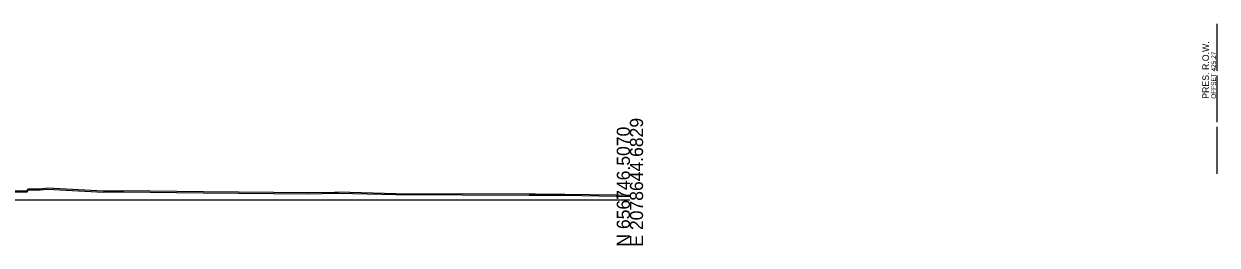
# Model space of a CAD drawing. Extents: x 5868 to 6683, y 2883 to 19120.
# Drawn here: x 6364.5 to 6619, y 18435.4 to 18482.6 of the extents above; entities that cross this region are included whole.
import ezdxf

# ---------------------------------------------------------------- set-up
doc = ezdxf.new("R2010")
doc.units = 0
for name, color, linetype in [('DESIGN - SHEET - Light Grid', 7, 'Continuous'), ('SURVEY - GROUND - Bottom of Topsoil Layer', 7, 'Continuous'), ('SURVEY - GROUND - Top of Ground', 7, 'Continuous'), ('SURVEY - PROPERTY - ROW Lines', 7, 'Continuous'), ('SURVEY - PROPERTY - ROW Lines Text', 7, 'Continuous')]:
    doc.layers.add(name, color=color, linetype=linetype)

msp = doc.modelspace()

# ---------------------------------------------------------------- linework, layer by layer
at = {"layer": 'DESIGN - SHEET - Light Grid'}
msp.add_line((6193.78, 18445.07), (6493.78, 18445.07), dxfattribs=at)
at = {"layer": 'SURVEY - GROUND - Bottom of Topsoil Layer'}
for p, q in [((6353.8, 18446.69), (6365.21, 18446.8)), ((6365.21, 18446.8), (6365.47, 18447.17)), ((6365.47, 18447.17), (6367.99, 18447.18)), ((6367.99, 18447.18), (6369.56, 18447.35)), ((6369.56, 18447.35), (6381.49, 18446.73)), ((6381.49, 18446.73), (6382.78, 18446.75)), ((6382.78, 18446.75), (6385.76, 18446.79)), ((6385.76, 18446.79), (6402.82, 18446.58)), ((6402.82, 18446.58), (6425.22, 18446.34)), ((6425.22, 18446.34), (6430.74, 18446.48)), ((6430.74, 18446.48), (6431.6, 18446.51)), ((6431.6, 18446.51), (6443.88, 18446.19)), ((6443.88, 18446.19), (6472.31, 18446.09)), ((6472.31, 18446.09), (6473.61, 18446.08)), ((6473.61, 18446.08), (6476.98, 18446.04)), ((6476.98, 18446.04), (6479.87, 18446.02)), ((6479.87, 18446.02), (6490.85, 18445.87)), ((6490.85, 18445.87), (6493.78, 18445.79))]:
    msp.add_line(p, q, dxfattribs=at)
at = {"layer": 'SURVEY - GROUND - Top of Ground'}
msp.add_lwpolyline([(6353.8, 18446.94), (6365.21, 18447.05), (6365.47, 18447.42), (6367.99, 18447.43), (6369.56, 18447.6), (6381.49, 18446.98), (6382.78, 18447), (6385.76, 18447.04), (6402.82, 18446.83), (6425.22, 18446.59), (6430.74, 18446.73), (6431.6, 18446.76), (6443.88, 18446.44), (6472.31, 18446.34), (6473.61, 18446.33), (6476.98, 18446.29), (6479.87, 18446.27), (6490.85, 18446.12), (6493.78, 18446.04)], dxfattribs=at)
at = {"layer": 'SURVEY - PROPERTY - ROW Lines'}
for p, q in [((6619.05, 18472.64), (6619.05, 18482.64)), ((6619.05, 18461.64), (6619.05, 18471.64)), ((6619.05, 18450.64), (6619.05, 18460.64))]:
    msp.add_line(p, q, dxfattribs=at)

# ---------------------------------------------------------------- texts
at = {"layer": 'DESIGN - SHEET - Light Grid'}
for s, p in [('N 656746.5070', (6493.78, 18435.07)), ('E 2078644.6829', (6496.58, 18435.07))]:
    msp.add_text(s, height=2.8, rotation=90, dxfattribs=at).set_placement(p)
at = {"layer": 'SURVEY - PROPERTY - ROW Lines Text'}
for s, height, p in [('PRES. R.O.W.', 1.4, (6617.3, 18466.64)), ('OFFSET 425.27', 1, (6618.8, 18466.64))]:
    msp.add_text(s, height=height, rotation=90, dxfattribs=at).set_placement(p)

doc.saveas('drawing.dxf')
